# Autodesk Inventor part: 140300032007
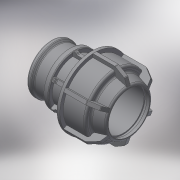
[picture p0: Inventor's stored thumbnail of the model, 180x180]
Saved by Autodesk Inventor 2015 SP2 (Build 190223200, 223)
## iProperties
Created: 2017-08
Part Number: 140300032007
Material: Generic
Description: PLASSON L.14 FEMALE ADAPTOR (SILVER) 32-3/4"
Document SubType Name: Modeling
Designer: KIM
Density: 1 g/cm^3
Appearance: Default
Author: KIM
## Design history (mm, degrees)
derived "140300.ipt"
feature "Solid1::140300.ipt"
tag "TaggingFeature1"
body "Solid1"
other parameters: "d1" = 32, "d2" = 61, "d4" = 15 deg, "d5" = 40.26, "d6" = 13.2858, "d9" = 24.117, "d10" = 61, "d11" = 31.3521, "d12" = 28.9404, "d13" = 43.4106, "d14" = 19, "d16" = 32.64, "d17" = 3.05, "d18" = 82, "d19" = 5.7, "d20" = 135 deg, "d21" = 5.7, "d22" = 36.1755, "d23" = 22.4, "d24" = 3.05, "d25" = 54.9, "d26" = 45.75, "d27" = 3.05, "d28" = 135 deg, "d29" = 1.83, "d31" = 1.6, "d44" = 0.64, "d45" = 0.96, "d46" = 150 deg, "d49" = 3.05, "d50" = 0, "d51" = 0.61, "d52" = 1.22, "d53" = 45 deg, "d55" = 7.812, "d56" = 3.05, "d57" = 0, "d58" = 0.96, "d61" = 360 deg, "d_" = 32, "G_" = 24.117, "E_" = 61, "H_" = 82, "l_" = 61, "l_2" = 19, "d54" = 19.53
